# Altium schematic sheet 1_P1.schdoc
size 431 x 309 mm
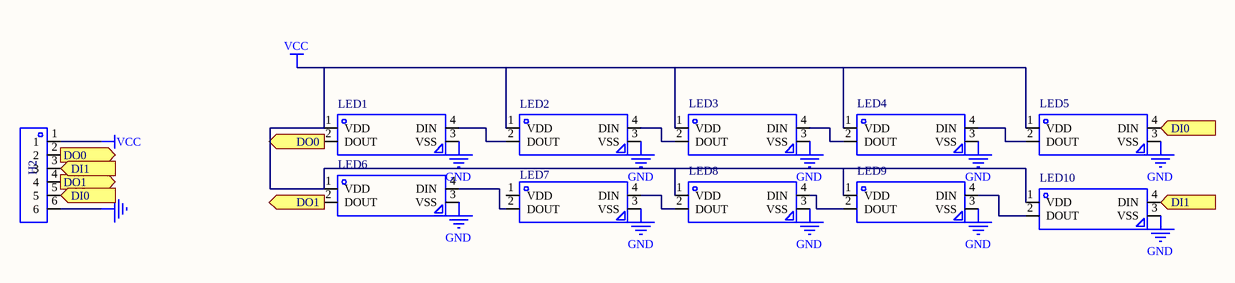
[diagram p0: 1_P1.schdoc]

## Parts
H2  (no value)  [HDR-TH_6P-P2.54-V-M-1]
LED1  (no value)  [LED-SMD_4P-L5.0-W5.0-TL_WS2812B-B]
LED2  (no value)  [LED-SMD_4P-L5.0-W5.0-TL_WS2812B-B]
LED3  (no value)  [LED-SMD_4P-L5.0-W5.0-TL_WS2812B-B]
LED4  (no value)  [LED-SMD_4P-L5.0-W5.0-TL_WS2812B-B]
LED5  (no value)  [LED-SMD_4P-L5.0-W5.0-TL_WS2812B-B]
LED6  (no value)  [LED-SMD_4P-L5.0-W5.0-TL_WS2812B-B]
LED7  (no value)  [LED-SMD_4P-L5.0-W5.0-TL_WS2812B-B]
LED8  (no value)  [LED-SMD_4P-L5.0-W5.0-TL_WS2812B-B]
LED9  (no value)  [LED-SMD_4P-L5.0-W5.0-TL_WS2812B-B]
LED10  (no value)  [LED-SMD_4P-L5.0-W5.0-TL_WS2812B-B]

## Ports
DI0 (in), DI1 (in), DO0 (out), DO1 (out)

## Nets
GND: H2.6 LED1.3(VSS) LED2.3(VSS) LED3.3(VSS) LED4.3(VSS) LED5.3(VSS) LED6.3(VSS) LED7.3(VSS) LED8.3(VSS) LED9.3(VSS) LED10.3(VSS)
VCC: H2.1 LED1.1(VDD) LED2.1(VDD) LED3.1(VDD) LED4.1(VDD) LED5.1(VDD) LED6.1(VDD) LED8.1(VDD) LED9.1(VDD) LED10.1(VDD)
DI0: H2.5 LED5.4(DIN) ; port DI0
DI1: H2.3 LED10.4(DIN) ; port DI1
DO0: H2.2 LED1.2(DOUT) ; port DO0
DO1: H2.4 LED6.2(DOUT) ; port DO1
NetLED1_4: LED1.4(DIN) LED2.2(DOUT)
NetLED2_4: LED2.4(DIN) LED3.2(DOUT)
NetLED3_4: LED3.4(DIN) LED4.2(DOUT)
NetLED4_4: LED4.4(DIN) LED5.2(DOUT)
NetLED6_4: LED6.4(DIN) LED7.2(DOUT)
NetLED7_4: LED7.4(DIN) LED8.2(DOUT)
NetLED8_4: LED8.4(DIN) LED9.2(DOUT)
NetLED9_4: LED9.4(DIN) LED10.2(DOUT)

Not connected (* = marked no-connect by the designer): LED7 1(VDD)

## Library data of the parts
H2 = A2541WV-6P: Manufacturer: CJT(长江连接器); Add into BOM: yes; Pitch: 2.54mm; Description: 额定电流:-;触头镀层:-;安装类型:直插;圆针/方针:-;额定电压:-;塑高:-;配合针长度:-;排数:1;总PIN位数:6;间距:2.54mm;触头材质:黄铜;行距:-;
LED1-LED10 = WS2812B-B: Manufacturer: worldsemi; Add into BOM: yes; Emitted Color: RGB三色; Description: 发光颜色:RGB三色;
